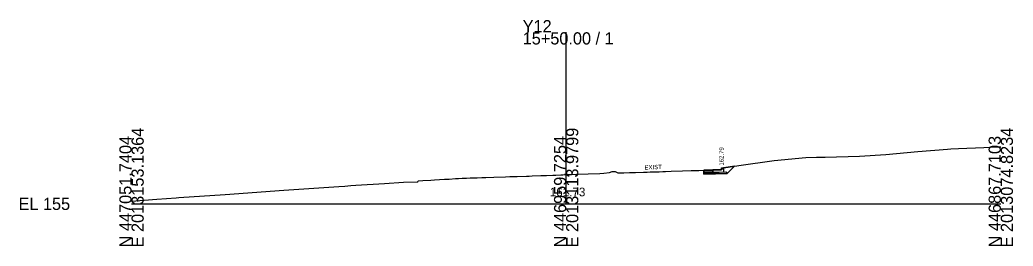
# Model space of a CAD drawing. Extents: x -26 to 1203, y -10 to 9542.
# Drawn here: x 974.3 to 1202.8, y 990.3 to 1042.2 of the extents above; entities that cross this region are included whole.
import ezdxf

# ---------------------------------------------------------------- set-up
doc = ezdxf.new("R2010")
doc.units = 0
for name, color, linetype in [('Default', 7, 'Continuous'), ('Exist Cross Section Cell', 7, 'Continuous'), ('Exist XS Center Line Elevation Label', 7, 'Continuous'), ('Exist XS Ground Line', 7, 'Continuous'), ('Prop CMT Conc Surface', 7, 'Continuous'), ('Prop CMT Concrete Structures', 7, 'Continuous'), ('Prop CMT Pvmt Course 1', 7, 'Continuous'), ('Prop CMT Pvmt Course 1 CG', 7, 'Continuous'), ('Prop CMT Pvmt Course 2', 7, 'Continuous'), ('Prop CMT Pvmt Course 3', 7, 'Continuous'), ('Prop CMT Pvmt Surface', 7, 'Continuous'), ('Prop CMT Slope Grass', 7, 'Continuous'), ('Prop CMT Subgrade Earthwork', 7, 'Continuous'), ('Prop XS Earthwork Shape', 7, 'Continuous'), ('Prop XS Hydro Elevations', 7, 'Continuous'), ('Prop XS SE Text', 7, 'Continuous')]:
    doc.layers.add(name, color=color, linetype=linetype)

msp = doc.modelspace()

# ---------------------------------------------------------------- linework, layer by layer
at = {"layer": 'Exist Cross Section Cell'}
for p, q in [((1100, 1000), (1100, 1039.4)), ((1000, 1000), (1100, 1000)), ((1100, 1000), (1200, 1000))]:
    msp.add_line(p, q, dxfattribs=at)
at = {"layer": 'Exist XS Ground Line'}
msp.add_lwpolyline([(1000, 1000.64), (1005.84, 1001.07), (1010.28, 1001.38), (1010.87, 1001.44), (1021.53, 1002.19), (1035.04, 1003.12), (1047.66, 1004), (1049.11, 1004.1), (1050.43, 1004.19), (1051.59, 1004.27), (1058.17, 1004.71), (1062.61, 1004.95), (1065.88, 1005.04), (1065.93, 1005.26), (1067.03, 1005.35), (1068.84, 1005.47), (1069.74, 1005.53), (1072, 1005.65), (1072.64, 1005.69), (1073.08, 1005.71), (1074.57, 1005.79), (1075.2, 1005.82), (1076.11, 1005.87), (1077.04, 1005.92), (1077.92, 1005.96), (1078.39, 1005.98), (1079.49, 1006.01), (1080.63, 1006.05), (1081.48, 1006.08), (1083.34, 1006.15), (1086.05, 1006.23), (1087.05, 1006.27), (1088.07, 1006.3), (1088.75, 1006.32), (1090.91, 1006.38), (1091.46, 1006.39), (1092.21, 1006.42), (1094.18, 1006.48), (1095.5, 1006.52), (1096.9, 1006.57), (1097.61, 1006.6), (1098.77, 1006.67), (1099.25, 1006.7), (1099.61, 1006.72), (1100, 1006.73), (1101.21, 1006.78), (1102.34, 1006.81), (1105.06, 1006.9), (1107.77, 1006.99), (1108.69, 1007.02), (1109.97, 1007.17), (1110.57, 1007.47), (1111.26, 1007.44), (1111.86, 1007.14), (1112.28, 1007.13), (1113.25, 1007.15), (1114.58, 1007.19), (1115.95, 1007.23), (1117.79, 1007.27), (1118.67, 1007.3), (1119.31, 1007.32), (1121.38, 1007.39), (1122.27, 1007.42), (1122.83, 1007.44), (1124.16, 1007.48), (1126.79, 1007.57), (1128.73, 1007.63), (1129.5, 1007.66), (1130.53, 1007.69), (1132.2, 1007.75), (1132.52, 1007.76), (1133.72, 1007.81), (1134.17, 1007.81), (1134.79, 1007.83), (1135.59, 1007.84), (1136.26, 1008.29), (1139.69, 1008.82), (1147.86, 1009.99), (1155.15, 1010.62), (1157.59, 1010.69), (1159.58, 1010.69), (1167.47, 1010.97), (1173.54, 1011.36), (1180.88, 1012), (1187.76, 1012.59), (1188.5, 1012.64), (1190.26, 1012.74), (1196.13, 1012.92), (1198.62, 1013.11), (1200, 1013.13)], dxfattribs=at)
at = {"layer": 'Prop CMT Conc Surface'}
msp.add_lwpolyline([(1133.72, 1007.81), (1135.72, 1007.79), (1135.72, 1008.29), (1136.22, 1008.29)], dxfattribs=at)
at = {"layer": 'Prop CMT Concrete Structures'}
for points in [[(1133.72, 1007.81), (1135.72, 1007.79), (1135.72, 1008.29), (1136.22, 1008.29)], [(1136.22, 1008.29), (1136.22, 1007.3), (1133.72, 1007.22)], [(1133.72, 1007.22), (1133.72, 1007.81)]]:
    msp.add_lwpolyline(points, dxfattribs=at)
at = {"layer": 'Prop CMT Pvmt Course 1'}
for points in [[(1131.71, 1007.74), (1133.72, 1007.81)], [(1131.71, 1007.74), (1131.71, 1007.74)], [(1131.71, 1007.49), (1131.71, 1007.74)], [(1133.72, 1007.56), (1131.71, 1007.49)], [(1133.72, 1007.81), (1133.72, 1007.56)]]:
    msp.add_lwpolyline(points, dxfattribs=at)
at = {"layer": 'Prop CMT Pvmt Course 1 CG'}
for points in [[(1133.72, 1007.22), (1136.72, 1007.32), (1137.04, 1007)], [(1133.72, 1006.89), (1133.72, 1007.22)], [(1137.04, 1007), (1133.72, 1006.89)]]:
    msp.add_lwpolyline(points, dxfattribs=at)
at = {"layer": 'Prop CMT Pvmt Course 2'}
for points in [[(1131.71, 1007.49), (1133.72, 1007.56)], [(1131.71, 1007.16), (1131.71, 1007.49)], [(1133.72, 1007.22), (1131.71, 1007.16)], [(1133.72, 1007.56), (1133.72, 1007.22)]]:
    msp.add_lwpolyline(points, dxfattribs=at)
at = {"layer": 'Prop CMT Pvmt Course 3'}
for points in [[(1131.71, 1007.16), (1133.72, 1007.22)], [(1131.71, 1006.82), (1131.71, 1007.16)], [(1133.72, 1006.89), (1131.71, 1006.82)], [(1133.72, 1007.22), (1133.72, 1006.89)]]:
    msp.add_lwpolyline(points, dxfattribs=at)
at = {"layer": 'Prop CMT Pvmt Surface'}
msp.add_lwpolyline([(1131.71, 1007.74), (1133.72, 1007.81)], dxfattribs=at)
at = {"layer": 'Prop CMT Slope Grass'}
msp.add_lwpolyline([(1136.22, 1008.29), (1138.71, 1008.67)], dxfattribs=at)
at = {"layer": 'Prop CMT Subgrade Earthwork'}
for points in [[(1133.72, 1006.89), (1137.04, 1007), (1138.71, 1008.67)], [(1131.71, 1006.82), (1131.71, 1007.74)], [(1131.71, 1006.82), (1133.72, 1006.89)], [(1133.72, 1006.89), (1131.71, 1006.82)]]:
    msp.add_lwpolyline(points, dxfattribs=at)
at = {"layer": 'Prop XS Earthwork Shape'}
msp.add_lwpolyline([(1131.71, 1007.74), (1131.71, 1006.82), (1137.04, 1007), (1138.71, 1008.67), (1136.26, 1008.29), (1135.59, 1007.84), (1134.79, 1007.83), (1133.72, 1007.81)], close=True, dxfattribs=at)

# ---------------------------------------------------------------- texts
at = {"layer": 'Default'}
msp.add_text('-', height=0.0001, dxfattribs=at).set_placement((1000, 1000))
at = {"layer": 'Exist Cross Section Cell'}
for s, p in [('Y12', (1090, 1039.4)), ('15+50.00 / 1', (1090, 1036.6)), ('EL 155', (974, 998.6))]:
    msp.add_text(s, height=2.8, dxfattribs=at).set_placement(p)
for s, p in [('E 2013153.1364', (1002.8, 990)), ('E 2013113.9799', (1102.8, 990)), ('E 2013074.8234', (1202.8, 990)), ('N 447051.7404', (1000, 990)), ('N 446959.7254', (1100, 990)), ('N 446867.7103', (1200, 990))]:
    msp.add_text(s, height=2.8, rotation=90, dxfattribs=at).set_placement(p)
at = {"layer": 'Exist XS Center Line Elevation Label'}
msp.add_text('161.73', height=2, dxfattribs=at).set_placement((1096.23, 1001.73))
at = {"layer": 'Prop XS Hydro Elevations'}
msp.add_text('162.79', height=1, rotation=90, dxfattribs=at).set_placement((1136.22, 1008.79))
at = {"layer": 'Prop XS SE Text'}
msp.add_text('EXIST', height=1, rotation=1.8605, dxfattribs=at).set_placement((1118.04, 1007.87))

doc.saveas('drawing.dxf')
